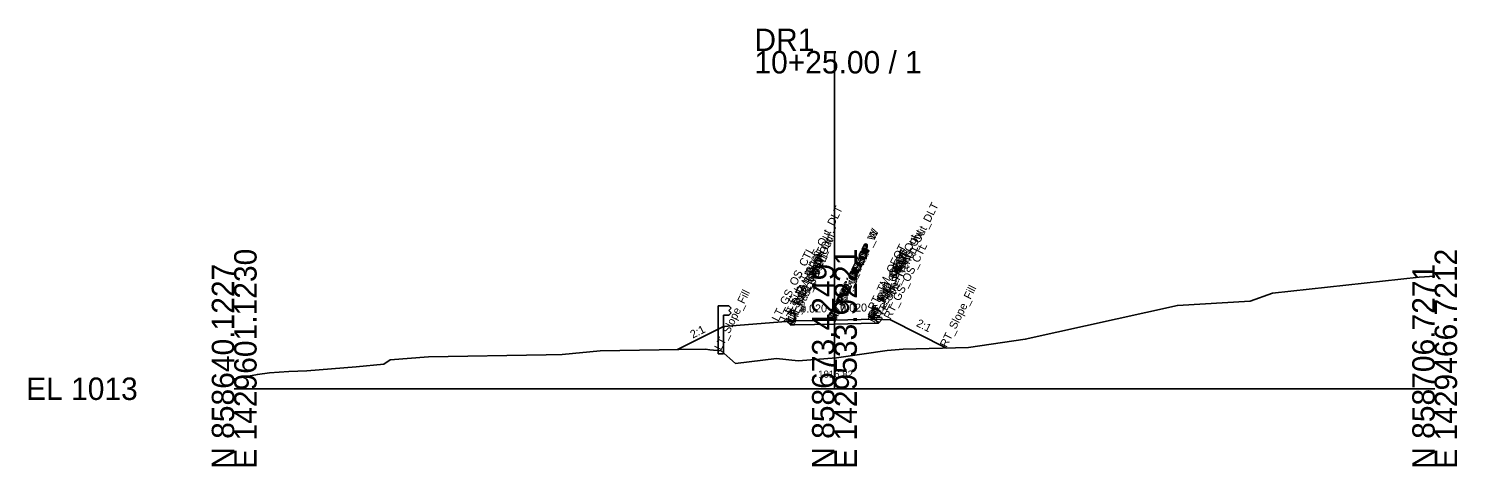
# Model space of a CAD drawing. Extents: x -26 to 1303, y -10 to 1029.
# Drawn here: x 1124.3 to 1302.8, y -9.7 to 45 of the extents above; entities that cross this region are included whole.
import ezdxf

# ---------------------------------------------------------------- set-up
doc = ezdxf.new("R2010")
doc.units = 0
for name, color, linetype in [('Default', 7, 'Continuous'), ('Exist Cross Section Cell', 7, 'Continuous'), ('Exist XS Center Line Elevation Label', 7, 'Continuous'), ('Exist XS Ground Line', 7, 'Continuous'), ('Prop CMT Guardrail Graphics', 7, 'Continuous'), ('Prop CMT Pvmt Course 1', 7, 'Continuous'), ('Prop CMT Pvmt Course 2', 7, 'Continuous'), ('Prop CMT Pvmt Surface', 7, 'Continuous'), ('Prop CMT Pvmt Surface Overlay', 7, 'Continuous'), ('Prop CMT Shld Paved Course 1', 7, 'Continuous'), ('Prop CMT Shld Paved Course 2', 7, 'Continuous'), ('Prop CMT Slope Grass', 7, 'Continuous'), ('Prop CMT Subgrade Earthwork', 7, 'Continuous'), ('Prop XS Dump Level', 7, 'Continuous'), ('Prop XS EOT Tick Mark', 7, 'Continuous'), ('Prop XS SE Text', 7, 'Continuous'), ('Prop XS Side Slope Text', 7, 'Continuous')]:
    doc.layers.add(name, color=color, linetype=linetype)

msp = doc.modelspace()

# ---------------------------------------------------------------- linework, layer by layer
at = {"layer": 'Exist Cross Section Cell'}
for p, q in [((1225, 0), (1225, 42.16)), ((1150, 0), (1225, 0)), ((1225, 0), (1300, 0))]:
    msp.add_line(p, q, dxfattribs=at)
at = {"layer": 'Exist XS Ground Line'}
msp.add_lwpolyline([(1150, 1.23), (1152.9, 1.79), (1154.41, 1.99), (1156.82, 2.14), (1159.09, 2.23), (1165.25, 2.75), (1168.69, 3.06), (1169.48, 3.63), (1174.28, 4), (1188.98, 4.23), (1190.98, 4.27), (1195.71, 4.73), (1205.54, 4.9), (1208.88, 4.94), (1209.41, 4.86), (1210.83, 4.72), (1212.65, 3.15), (1217.76, 3.76), (1220.46, 3.48), (1225.24, 3.84), (1231.57, 4.77), (1233.6, 4.96), (1241.75, 5.16), (1248.84, 6.18), (1267.85, 10.4), (1276.93, 10.95), (1279.72, 11.95), (1298.06, 13.92), (1300, 14.05)], dxfattribs=at)
at = {"layer": 'Prop CMT Guardrail Graphics'}
for points in [[(1210.47, 4.34), (1210.47, 10.34)], [(1210.47, 10.34), (1211.81, 10.34), (1212.08, 10.05)], [(1212.08, 9.47), (1211.81, 9.18), (1211.14, 9.18)], [(1211.14, 9.18), (1211.14, 4.34)], [(1212.08, 10.05), (1211.81, 9.76)], [(1211.81, 9.76), (1212.08, 9.47)], [(1211.14, 4.34), (1210.47, 4.34)]]:
    msp.add_lwpolyline(points, dxfattribs=at)
at = {"layer": 'Prop CMT Pvmt Course 1'}
for points in [[(1225, 8.57), (1220, 8.47)], [(1225, 8.57), (1230, 8.67)]]:
    msp.add_lwpolyline(points, dxfattribs=at)
at = {"layer": 'Prop CMT Pvmt Course 2'}
for points in [[(1220, 7.97), (1225, 8.07)], [(1230, 8.17), (1225, 8.07)]]:
    msp.add_lwpolyline(points, dxfattribs=at)
at = {"layer": 'Prop CMT Pvmt Surface'}
for points in [[(1225, 8.57), (1220, 8.47)], [(1225, 8.57), (1230, 8.67)]]:
    msp.add_lwpolyline(points, dxfattribs=at)
at = {"layer": 'Prop CMT Pvmt Surface Overlay'}
for points in [[(1225, 8.57), (1220, 8.47)], [(1225, 8.57), (1230, 8.67)]]:
    msp.add_lwpolyline(points, dxfattribs=at)
at = {"layer": 'Prop CMT Shld Paved Course 1'}
for points in [[(1220, 8.47), (1219.74, 8.21)], [(1230, 8.67), (1230.25, 8.42)]]:
    msp.add_lwpolyline(points, dxfattribs=at)
at = {"layer": 'Prop CMT Shld Paved Course 2'}
for points in [[(1219.74, 8.21), (1219.49, 7.96)], [(1219.49, 7.96), (1220, 7.97)], [(1219.74, 8.21), (1219.74, 8.21)], [(1230.49, 8.18), (1230, 8.17)], [(1230.25, 8.42), (1230.25, 8.42)], [(1230.25, 8.42), (1230.49, 8.18)]]:
    msp.add_lwpolyline(points, dxfattribs=at)
at = {"layer": 'Prop CMT Slope Grass'}
for p, q in [((1211.14, 7.77), (1205.39, 4.89)), ((1220, 8.48), (1211.14, 7.77))]:
    msp.add_line(p, q, dxfattribs=at)
msp.add_lwpolyline([(1230, 8.67), (1232, 8.59), (1239.02, 5.08)], dxfattribs=at)
at = {"layer": 'Prop CMT Subgrade Earthwork'}
for points in [[(1225, 8.07), (1220, 7.97), (1219.49, 7.96), (1219.06, 8.39)], [(1225, 8.07), (1230, 8.17), (1230.49, 8.18), (1230.94, 8.63)]]:
    msp.add_lwpolyline(points, dxfattribs=at)
at = {"layer": 'Prop XS EOT Tick Mark'}
for points in [[(1220, 8.47), (1220, 9.47)], [(1230, 8.67), (1230, 9.67)]]:
    msp.add_lwpolyline(points, dxfattribs=at)

# ---------------------------------------------------------------- texts
at = {"layer": 'Default'}
msp.add_text('-', height=0.0001, dxfattribs=at).set_placement((1150, 0))
at = {"layer": 'Exist Cross Section Cell'}
for s, p in [('DR1', (1215, 42.16)), ('10+25.00 / 1', (1215, 39.36)), ('EL 1013', (1124, -1.4))]:
    msp.add_text(s, height=2.8, dxfattribs=at).set_placement(p)
for s, p in [('E 1429601.1230', (1152.8, -10)), ('E 1429533.9221', (1227.8, -10)), ('E 1429466.7212', (1302.8, -10)), ('N 858640.1227', (1150, -10)), ('N 858673.4249', (1225, -10)), ('N 858706.7271', (1300, -10))]:
    msp.add_text(s, height=2.8, rotation=90, dxfattribs=at).set_placement(p)
at = {"layer": 'Exist XS Center Line Elevation Label'}
msp.add_text('1016.82', height=0.9, dxfattribs=at).set_placement((1222.96, 1.37))
at = {"layer": 'Prop XS Dump Level'}
for s, p in [('RT_Sub_Trench_Out_DLT', (1230.94, 8.63)), ('LT_Sub_Trench_Out_DLT', (1219.06, 8.39)), ('RT_PV1_OEEOP_W', (1225, 8.44)), ('LT_PV1_OEEOP_W', (1225, 8.44)), ('RT_Sub_Trench_Out', (1230.49, 8.18)), ('LT_Sub_Trench_Out', (1219.49, 7.96)), ('LT_PS2_Shelf_Out', (1219.74, 8.21)), ('RT_PV2_OEEOP', (1225, 8.32)), ('LT_PV2_OEEOP', (1225, 8.32)), ('RT_TM_OEOT', (1230, 9.67)), ('RT_PS2_Shelf_Out', (1230.25, 8.42)), ('RT_GS_OS_CTL', (1232, 8.59)), ('LT_GS_OS_CTL', (1218, 8.31)), ('LT_PS2_OEOP', (1219.74, 8.21)), ('LT_TM_OEOT', (1220, 9.47)), ('LT_PV1_OEOT', (1220, 8.47)), ('LT_PV2_OEOT', (1220, 8.22)), ('LT_Sub_OEOT', (1220, 7.97)), ('RT_Sub_OEEOP', (1225, 8.07)), ('LT_Sub_OEEOP', (1225, 8.07)), ('RT_PV1_OEOT', (1230, 8.67)), ('RT_PV2_OEOT', (1230, 8.42)), ('RT_Sub_OEOT', (1230, 8.17)), ('RT_PS2_OEOP', (1230.25, 8.42)), ('PV1_PGL_W', (1225, 8.44)), ('PV1_PGL', (1225, 8.57)), ('RT_Slope_Fill', (1239.02, 5.08)), ('LT_Slope_Fill', (1210.83, 4.72))]:
    msp.add_text(s, height=1, rotation=63.5833, dxfattribs=at).set_placement(p)
at = {"layer": 'Prop XS SE Text'}
for p in [(1220.73, 9.48), (1225.73, 9.58)]:
    msp.add_text('0.020', height=1, rotation=1.1458, dxfattribs=at).set_placement(p)
at = {"layer": 'Prop XS Side Slope Text'}
for rotation, p in [(26.5651, (1207.29, 6.25)), (333.4349, (1235.14, 7.86))]:
    msp.add_text('2:1', height=1, rotation=rotation, dxfattribs=at).set_placement(p)

doc.saveas('drawing.dxf')
